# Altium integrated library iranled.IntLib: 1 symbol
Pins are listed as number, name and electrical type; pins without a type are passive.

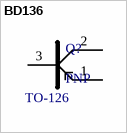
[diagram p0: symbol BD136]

## BD136
designator Q?, comment PNP  Package: TO-126
FORUM: IRANLED.COM
footprint PCBComponent_1
pins: 1, 2, 3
